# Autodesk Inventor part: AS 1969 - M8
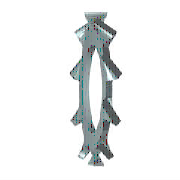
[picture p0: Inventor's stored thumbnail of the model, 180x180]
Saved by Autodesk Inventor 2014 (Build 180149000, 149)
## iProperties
IsCustomPart: 0
Created: 2008-02
Part Number: AS 1969 - M8
Material: Steel, Mild
Description: Metric Tooth LW
Document SubType Name: Modeling
Standard: AS 1969
Designer: PN
Standards Organization: AS
Language: en-US
Size Designation: M8
Categories: <MemberInstance><Categories><Category DisplayName="Fasteners" InternalName="e4da775c-781d-43d5-af7c-5136215cf5a6" Mnemonic="FSTN"><Category DisplayName="Washers
Density: 7.86 g/cm^3
Mass: 0.474048 g
Surface Area: 2.15852 cm^2
Volume: 0.0603114 cm^3
Appearance: Steel
Author: PN
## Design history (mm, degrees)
sketch "Sketch1"
  geometry: C1 r 7 at (0, 0); C2 r 4.2 at (0, 0)
  constraints: 2 centre point, 1 coincident, 1 other
  dimensions: "d0" = 14 diameter of C1 (= SD2); "d1" = 8.4 diameter of C2 (= SD1)
extrude "Body" new body sketch "Sketch1" distance "d2" = 0.85 (= SD); taper "d3" = 0 deg
sketch "Sketch2"
  geometry: L1 (0, 0)-(0, 7); L2 (-1.093, 5.492)-(-1.366, 6.865); L3 (1.093, 5.492)-(1.366, 6.865); L4 (-1.093, 5.492)-(0, 0); L5 (0, 0)-(1.093, 5.492); A1 r 7 centre (0, 0) between (0, 7) and (1.366, 6.865) reference; A2 r 7 centre (0, 0) between (1.366, 6.865) and (-1.366, 6.865); A3 r 5.6 centre (0, 0) between (1.093, 5.492) and (-1.093, 5.492)
  constraints: 10 end point, 7 point on circle, 2 centre point, 2 coincident, 2 collinear, 1 concentric, 1 symmetric about line, 1 vertical
  dimensions: "d4" = 22.5 deg angle of L3 L2 (computed from SAZ); "d5" = 11.2 diameter of A3 (= 0.5 x SD2 + 0.5 x SD1)
extrude "Cut" cut sketch "Sketch2" stored distance "d6" = 0.85 (= SD); taper "d7" = 0 deg
pattern_circular "Cuts" dims angle "d11" = 360 deg
workaxis "Work Axis1"
workplane "Work Plane1"
body "Solid1"
fillet "Fillet1" dims "d8" = 0.21 (= 0.015 x SD2)
other parameters: "SD" = 0.85 [user parameter; used in 2 equation terms], "SD1" = 8.4 [user parameter; used in 2 equation terms], "SD2" = 14 [user parameter; used in 3 equation terms], "NND" = 8 [user parameter], "d12" = 0, "d13" = 0, "d14" = 0, "d15" = 0, "d16" = 90 deg
